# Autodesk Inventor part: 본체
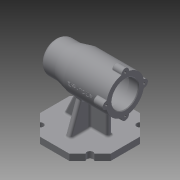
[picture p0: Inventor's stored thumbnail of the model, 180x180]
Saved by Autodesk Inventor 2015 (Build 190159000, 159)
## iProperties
Created: 2019-12
Part Number: 본체
Material: 일반
Document SubType Name: Modeling
Designer: now
Density: 1 g/cm^3
Appearance: 기본값
Author: now
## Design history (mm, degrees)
sketch "스케치1" dims "d0" = 112
  geometry: L1 (23.196, -56)-(-23.196, -56); L2 (-23.196, -56)-(-56, -23.196); L3 (-56, -23.196)-(-56, 23.196); L4 (-56, 23.196)-(-23.196, 56); L5 (-23.196, 56)-(23.196, 56); L6 (23.196, 56)-(56, 23.196); L7 (56, 23.196)-(56, -23.196); L8 (56, -23.196)-(23.196, -56); 4 further points
  constraints: 16 end point, 2 coincident, 1 midpoint, 1 vertical, 20 other
extrude "돌출1" new body sketch "스케치1" distance "d1" = 10; taper "d2" = 0 deg
sketch "스케치2"
  geometry: L1 (-56, -23.196)-(-23.196, -56) reference; L2 (0, 0)-(-67.03, -67.03); L3 (0, 0)-(0, -69.123); C1 r 5 at (-39.598, -39.598)
  constraints: 4 end point, 1 centre point, 1 midpoint, 1 point on line, 1 vertical
  dimensions: "d3" = 45 deg angle of L3 L2; "d4" = 10 diameter of C1
extrude "돌출2" cut sketch "스케치2" stored distance "d5" = 10; taper "d6" = 0 deg
sketch "스케치3"
  geometry: L1 (-56, 23.196)-(-56, -23.196) reference; L2 (-23.196, -56)-(23.196, -56) reference; L3 (56, -23.196)-(56, 23.196) reference; L4 (23.196, 56)-(-23.196, 56) reference; L5 (-38, -4)-(31, -4); L6 (31, -4)-(31, 4); L7 (31, 4)-(-38, 4); L8 (-38, 4)-(-38, -4); L9 (-4, -36)-(4, -36); L10 (4, -36)-(4, 36); L11 (4, 36)-(-4, 36); L12 (-4, 36)-(-4, -36); 1 further point
  constraints: 16 end point, 4 parallel, 2 horizontal, 2 perpendicular
  dimensions: "d10" = 4 distance from line of L5 point (0, 0); "d11" = 8 distance between parallel lines of L5 L7; "d12" = 4 distance from line of point (0, 0) L12; "d13" = 8 distance between parallel lines of L10 L12; "d14" = 20 distance between parallel lines of L2 L9; "d15" = 20 distance between parallel lines of L11 L4; "d16" = 25 distance between parallel lines of L3 L6; "d17" = 18 distance between parallel lines of L1 L8
extrude "돌출3" join sketch "스케치3" distance "d18" = 70; taper "d19" = 0 deg
feature "면 기울기1" dims angle "d20" = 20 deg
feature "면 기울기2" dims angle "d21" = 25 deg
sketch "스케치4"
  geometry: L1 (56, 0)-(-56, 0) reference; L2 (-56, 0)-(-56, 10) reference; L3 (-56, 10)-(-31, 10) reference; L4 (-31, 10)-(-31, 80) reference; L5 (-31, 80)-(5.358, 80) reference; L6 (5.358, 80)-(38, 10) reference; L7 (38, 10)-(56, 10) reference; L8 (56, 10)-(56, 0) reference; L9 (-56, 80)-(56, 80); L10 (56, 80)-(56, 105); L11 (11, 110)-(-56, 110); L12 (-56, 110)-(-56, 80); L13 (11, 110)-(31, 105); L14 (31, 105)-(56, 105); 1 further point
  constraints: 12 end point, 2 horizontal, 2 parallel, 1 collinear, 1 perpendicular
  dimensions: "d22" = 0 horizontal distance of L1.end L9.start; "d23" = 30 distance of L11.end L9.start; "d24" = 112 distance between parallel lines of L10 L12; "d25" = 67 distance of L11.start L11.end; "d26" = 25 distance of L13.end L10.end; "d27" = 25 distance between parallel lines of L9 L14
revolve "회전1" sketch "스케치4" stored, may be unused: angle "d28" = 90 deg
sketch "스케치5"
  geometry: C1 r 30 at (0, 0) reference; C2 r 21 at (0, 0); 1 further point
  constraints: 1 centre point, 1 coincident
  dimensions: "d29" = 42 diameter of C2
extrude "돌출4" cut sketch "스케치5" distance "d30" = 15; taper "d31" = 0 deg
sketch "스케치6"
  geometry: C1 r 21 at (0, 0) reference; C2 r 24 at (0, 0); 1 further point
  constraints: 1 centre point, 1 coincident
  dimensions: "d32" = 48 diameter of C2
extrude "돌출5" cut sketch "스케치6" distance "d33" = 54; taper "d34" = 0 deg
sketch "스케치7"
  geometry: C1 r 24 at (0, 0) reference; C2 r 21 at (0, 0); 1 further point
  constraints: 1 centre point, 1 coincident
  dimensions: "d35" = 42 diameter of C2
extrude "돌출6" cut sketch "스케치7" distance "d36" = 12; taper "d37" = 0 deg
sketch "스케치8"
  geometry: C1 r 21 at (0, 0) reference; C2 r 17.5 at (0, 0); 1 further point
  constraints: 1 centre point, 1 coincident
  dimensions: "d38" = 35 diameter of C2
extrude "돌출7" cut sketch "스케치8" distance "d39" = 18; taper "d40" = 0 deg
sketch "스케치9"
  geometry: C1 r 17.5 at (0, 0) reference; C2 r 16 at (0, 0); 1 further point
  constraints: 1 centre point, 1 coincident
  dimensions: "d41" = 32 diameter of C2
extrude "돌출8" cut sketch "스케치9" distance "d42" = 4; taper "d43" = 0 deg
sketch "스케치10"
  geometry: C1 r 16 at (0, 0) reference; C2 r 10.5 at (0, 0); 1 further point
  constraints: 1 centre point, 1 coincident
  dimensions: "d44" = 21 diameter of C2
extrude "돌출9" cut sketch "스케치10" distance "d45" = 3; taper "d46" = 0 deg
fillet "모깎기1" dims "d47" = 0.3
sketch "스케치11"
  geometry: C1 r 21 at (0, 0) reference; C2 r 6 at (-30, 0); 2 further points
  constraints: 1 centre point, 1 coincident, 1 horizontal alignment
  dimensions: "d49" = 30 distance of C1.centre point (-30, 0); "d50" = 6 radius of C2
extrude "돌출10" join sketch "스케치11" distance "d51" = 16; taper "d52" = 0 deg
fillet "모깎기3" dims "d53" = 3
fillet "모깎기4" dims "d54" = 1
fillet "모깎기5" dims "d55" = 3
sketch "스케치12"
  geometry: A1 r 6 centre (0, 0) between (-0.171, 5.998) and (-0.171, -5.998) reference; 1 further point
hole "구멍1" sketch "스케치12" at (0, 0) diameter "d56" = 3.242; stored, may be unused: countersink angle "d60" = 90 deg, drill point angle "d62" = 118 deg; dims "d57" = 8, "d58" = 4, "d59" = 2, "d61" = 11
fillet "모깎기6" dims "d66" = 3
fillet "모깎기7" dims "d67" = 3
fillet "모깎기8" dims "d68" = 10
fillet "모깎기9" dims "d69" = 3
fillet "모깎기10" dims "d70" = 3
chamfer "모따기1" distance "d71" = 1; stored, may be unused: second distance "d72" = 2, angle "d73" = 45 deg
node "작업 평면2"
  node "작업 평면1"
sketch "스케치13"
  geometry: 1 further point
sketch "스케치14"
  geometry: L1 (33.5, 5.998)-(33.5, -5.998) reference; L2 (33.5, 29.226)-(33.5, 6.771) reference; 3 further points
  constraints: 1 horizontal alignment, 1 midpoint, 1 other
  dimensions: "d75" = 41 distance from line of L2 point (-7.5, 0)
feature "엠보싱1" sketch "스케치14" dims "d0" = 112, "d76" = 0.5, "d77" = 0
node "솔리드1"
pattern_circular "원형 패턴1" dims angle "d8" = 360 deg
pattern_circular "원형 패턴2" dims "d64" = 360 deg
node "절단 모서리 투영1"
